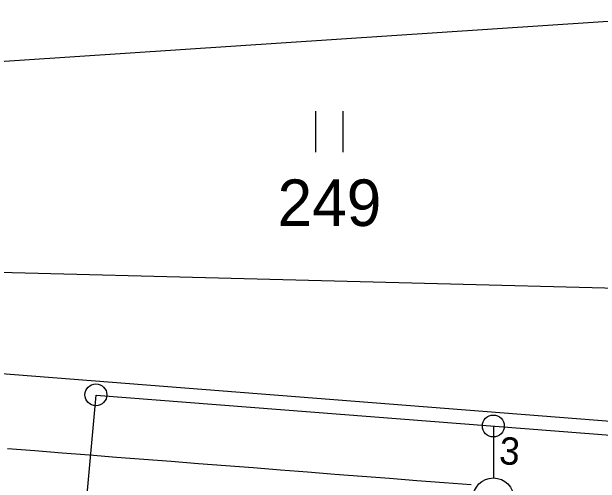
# Model space of a CAD drawing. Extents: x -670359 to -668019, y -978807 to -976674.
# Drawn here: x -669522.25 to -669500.74, y -977137.97 to -977120.74 of the extents above; entities that cross this region are included whole.
import ezdxf

# ---------------------------------------------------------------- set-up
doc = ezdxf.new("R2010")
doc.units = 0
for name, color, linetype in [('Hranice parcel', 7, 'Continuous'), ('Parcelní čísla', 7, 'Continuous'), ('SO 01-86-01', 7, 'Continuous'), ('SO 11-10-01', 7, 'Continuous'), ('SO 11-11-01', 7, 'Continuous'), ('Značky kultur', 7, 'Continuous')]:
    doc.layers.add(name, color=color, linetype=linetype)

# ---------------------------------------------------------------- blocks, each defined once
blk = doc.blocks.new('POINT_DISPLAY')
blk.add_line((0, 0), (0, 0))

msp = doc.modelspace()

# ---------------------------------------------------------------- linework, layer by layer
at = {"layer": 'Hranice parcel'}
for points in [[(-669495.11, -977120.74), (-669525.65, -977122.76)], [(-669495.86, -977130.97), (-669526.01, -977130.19)]]:
    msp.add_lwpolyline(points, dxfattribs=at)
at = {"layer": 'SO 01-86-01'}
for p, q in [((-669520.014, -977144.295), (-669519.163, -977134.751)), ((-669519.163, -977134.751), (-669492.657, -977136.821)), ((-669504.645, -977135.881), (-669504.645, -977137.381)), ((-669504.645, -977136.281), (-669504.645, -977137.781))]:
    msp.add_line(p, q, dxfattribs=at)
for centre, radius in [((-669519.171, -977134.741), 0.4), ((-669504.645, -977135.881), 0.4), ((-669504.645, -977138.531), 0.75)]:
    msp.add_circle(centre, radius, dxfattribs=at)
at = {"layer": 'SO 11-10-01'}
for p, q in [((-669522.401, -977136.706), (-669521.404, -977136.783)), ((-669521.404, -977136.783), (-669520.407, -977136.861)), ((-669520.407, -977136.861), (-669519.41, -977136.939)), ((-669519.41, -977136.939), (-669518.413, -977137.016)), ((-669518.413, -977137.016), (-669517.416, -977137.094)), ((-669517.416, -977137.094), (-669516.419, -977137.171)), ((-669516.419, -977137.171), (-669515.422, -977137.249)), ((-669515.422, -977137.249), (-669514.425, -977137.327)), ((-669514.425, -977137.327), (-669513.428, -977137.404)), ((-669513.428, -977137.404), (-669512.431, -977137.482)), ((-669512.431, -977137.482), (-669511.434, -977137.559)), ((-669511.434, -977137.559), (-669510.437, -977137.637)), ((-669510.437, -977137.637), (-669509.44, -977137.715)), ((-669509.44, -977137.715), (-669508.443, -977137.792)), ((-669508.443, -977137.792), (-669507.446, -977137.87)), ((-669507.446, -977137.87), (-669506.449, -977137.947)), ((-669506.449, -977137.947), (-669505.452, -977138.025))]:
    msp.add_line(p, q, dxfattribs=at)
at = {"layer": 'SO 11-11-01'}
msp.add_line((-669495.771, -977136.07), (-669530.167, -977133.393), dxfattribs=at)
at = {"layer": 'Značky kultur'}
for p, q in [((-669511.14, -977124.37), (-669511.14, -977125.87)), ((-669510.14, -977125.87), (-669510.14, -977124.37))]:
    msp.add_line(p, q, dxfattribs=at)

# ---------------------------------------------------------------- block references
at = {"layer": 'SO 01-86-01', "rotation": 4.450857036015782}
msp.add_blockref('POINT_DISPLAY', (-669504.675, -977135.896), dxfattribs=at)

# ---------------------------------------------------------------- texts
at = {"layer": 'Parcelní čísla'}
msp.add_text('249', height=1.7, dxfattribs=at).set_placement((-669512.533, -977128.57))
at = {"layer": 'SO 01-86-01'}
msp.add_text('3', height=1, rotation=356.1, dxfattribs=at).set_placement((-669504.454, -977137.27))

doc.saveas('drawing.dxf')
